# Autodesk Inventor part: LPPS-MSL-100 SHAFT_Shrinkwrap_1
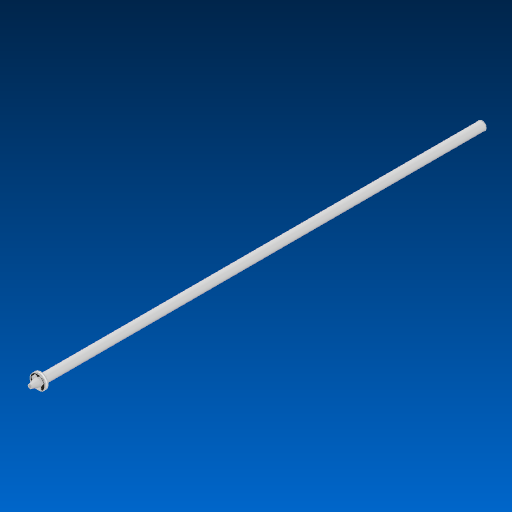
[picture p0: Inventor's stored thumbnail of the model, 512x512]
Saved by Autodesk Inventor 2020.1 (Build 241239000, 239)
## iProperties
Created: 2019-07
Part Number: LPPS-MSL-100 SHAFT_Shrinkwrap_1
Material: Generic
Document SubType Name: Modeling
Designer: J. Nielson
Density: 1 g/cm^3
Appearance: Default
Author: J. Nielson
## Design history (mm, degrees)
node "Assembly1" dims "d0" = 10
body "Solid1"
node "Part1:1" dims "d0" = 10
node "Part2:1" dims "d0" = 10
body "Solid2"
node "Part3:1" dims "d0" = 10
body "Solid3"
